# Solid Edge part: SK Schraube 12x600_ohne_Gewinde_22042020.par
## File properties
Author: fknapp
Template: Normal.par
Last saved by: fknapp
Revision: 43
Application: Solid Edge
Username: fknapp
Material: Aluminium
Genauigkeit: 0,99
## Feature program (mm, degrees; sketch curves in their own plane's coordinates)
sketch for "unnamed RevolvedProtrusion 1" plane through (0, 0, 0) normal (0, 0, 1) x-axis (1, 0, 0)
  line (0, 54) -> (11.25, 54)
  line (11.25, 54) -> (11.25, 53)
  line (11.25, 53) -> (6, 47.75)
  line (6, -533) -> (6, 47.75)
  line (0.5, -546) -> (6, -533)
  line (0, -546) -> (0.5, -546)
revolve "unnamed RevolvedProtrusion 1" add full turn 360 deg about sketch line (0, 54) -> (0, -546)
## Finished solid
Body 1: solid body, 6 faces, 5 edges, 0 vertices.
  Faces by surface: cone 2, cylinder 2, plane 2
  Edges by curve: circle 5
Bounding box of the edges (mm): 22.500 x 600.000 x 22.500, from (-11.25, -546, -11.25) to (11.25, 54, 11.25).
Cylindrical faces by radius (mm): R6 x1, R11.25 x1
Conical faces (half-angle, radius in mm at the cone's reference point): 22.9321 deg R6 x1, 45 deg R11.25 x1
Planar faces by outward normal: +y 1, -y 1
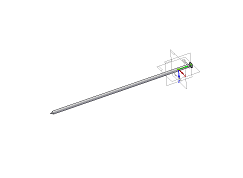
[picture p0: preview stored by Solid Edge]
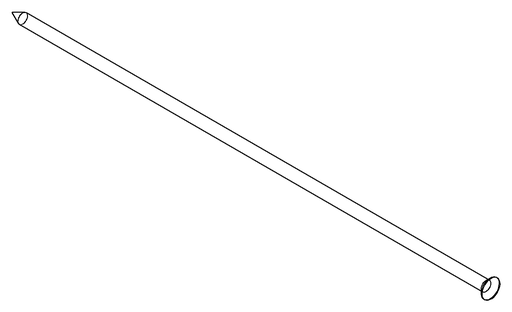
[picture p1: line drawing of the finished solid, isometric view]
